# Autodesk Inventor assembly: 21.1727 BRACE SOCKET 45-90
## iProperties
Created: 2007-04
Part Number: 21.1727 BRACE SOCKET 45-90
Document SubType Name: Assembly
Designer: Andy Moles
Author: Andy Moles
